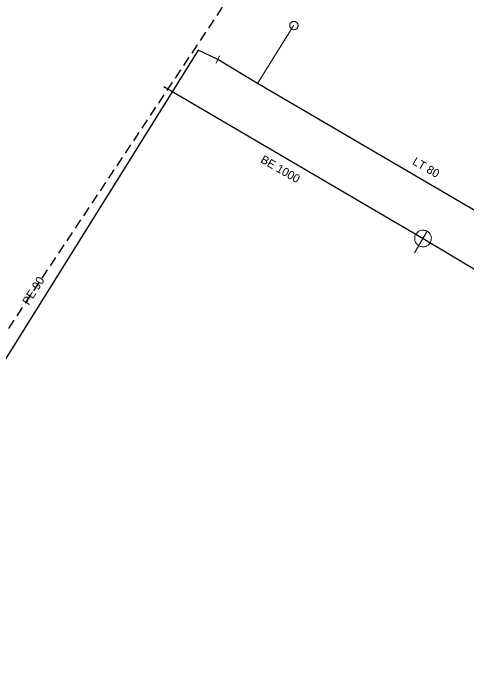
# Model space of a CAD drawing. Extents: x -791337 to -790755, y -988454 to -987923.
# Drawn here: x -791283 to -791228.7, y -988043.6 to -987964.2 of the extents above; entities that cross this region are included whole.
import ezdxf

# ---------------------------------------------------------------- set-up
doc = ezdxf.new("R2010")
doc.units = 0
doc.header["$LTSCALE"] = 0.4
doc.linetypes.add('MEDIUM_DASHED', pattern=[4.5, 3, -1.5])
for name, color, linetype, lineweight in [('1', 7, 'Continuous', 13), ('13', 7, 'Continuous', 13), ('14', 7, 'Continuous', 25), ('17', 7, 'Continuous', 25), ('22', 7, 'Continuous', 13), ('23', 7, 'Continuous', 13), ('34', 7, 'Continuous', 13), ('63', 7, 'MEDIUM_DASHED', 25)]:
    doc.layers.add(name, color=color, linetype=linetype, lineweight=lineweight)

msp = doc.modelspace()

# ---------------------------------------------------------------- linework, layer by layer
at = {"layer": '13'}
msp.add_line((-791249.419, -987965.689), (-791253.76, -987972.659), dxfattribs=at)
at = {"layer": '14'}
for p, q in [((-791265, -987973), (-791233.94, -987991.21)), ((-791233.94, -987991.21), (-791199.109, -988012.02))]:
    msp.add_line(p, q, dxfattribs=at)
at = {"layer": '17'}
for points in [[(-791258.52, -987969.789), (-791260.859, -987968.66), (-791297.14, -988026.69), (-791304.129, -988037.219)], [(-791197.89, -988005.699), (-791208.364, -987999.238), (-791208.76, -987998.997), (-791217.801, -987993.705), (-791253.76, -987972.659), (-791258.52, -987969.789)]]:
    msp.add_lwpolyline(points, dxfattribs=at)
at = {"layer": '22'}
msp.add_line((-791234.951, -987992.935), (-791233.434, -987990.347), dxfattribs=at)
msp.add_lwpolyline([(-791233.077, -987991.716), (-791233.027, -987991.619), (-791232.988, -987991.516), (-791232.96, -987991.41), (-791232.944, -987991.302), (-791232.94, -987991.192), (-791232.948, -987991.083), (-791232.968, -987990.975), (-791232.999, -987990.871), (-791233.042, -987990.77), (-791233.095, -987990.675), (-791233.159, -987990.585), (-791233.233, -987990.504), (-791233.314, -987990.431), (-791233.403, -987990.367), (-791233.499, -987990.313), (-791233.599, -987990.27), (-791233.704, -987990.238), (-791233.811, -987990.218), (-791233.921, -987990.21), (-791234.029, -987990.214), (-791234.138, -987990.23), (-791234.244, -987990.257), (-791234.347, -987990.297), (-791234.444, -987990.346), (-791234.535, -987990.407), (-791234.619, -987990.477), (-791234.696, -987990.556), (-791234.762, -987990.642), (-791234.82, -987990.736), (-791234.866, -987990.835), (-791234.902, -987990.938), (-791234.926, -987991.045), (-791234.938, -987991.153), (-791234.939, -987991.263), (-791234.926, -987991.372), (-791234.903, -987991.479), (-791234.868, -987991.583), (-791234.821, -987991.682), (-791234.765, -987991.775), (-791234.698, -987991.862), (-791234.622, -987991.941), (-791234.538, -987992.011), (-791234.446, -987992.072), (-791234.349, -987992.122), (-791234.247, -987992.161), (-791234.142, -987992.189), (-791234.033, -987992.205), (-791233.923, -987992.21), (-791233.814, -987992.202), (-791233.706, -987992.182), (-791233.601, -987992.151), (-791233.501, -987992.108), (-791233.405, -987992.055), (-791233.316, -987991.991), (-791233.234, -987991.919), (-791233.161, -987991.837), (-791233.097, -987991.748)], close=True, dxfattribs=at)
at = {"layer": '23'}
for points in [[(-791249.157, -987965.289), (-791249.203, -987965.265), (-791249.253, -987965.245), (-791249.302, -987965.233), (-791249.354, -987965.224), (-791249.406, -987965.22), (-791249.459, -987965.223), (-791249.51, -987965.231), (-791249.56, -987965.244), (-791249.61, -987965.262), (-791249.656, -987965.285), (-791249.701, -987965.313), (-791249.743, -987965.346), (-791249.78, -987965.382), (-791249.812, -987965.422), (-791249.842, -987965.465), (-791249.866, -987965.513), (-791249.885, -987965.56), (-791249.899, -987965.613), (-791249.908, -987965.662), (-791249.912, -987965.715), (-791249.908, -987965.769), (-791249.901, -987965.82), (-791249.887, -987965.871), (-791249.87, -987965.92), (-791249.847, -987965.966), (-791249.817, -987966.011), (-791249.786, -987966.051), (-791249.749, -987966.088), (-791249.708, -987966.121), (-791249.665, -987966.151), (-791249.619, -987966.175), (-791249.57, -987966.194), (-791249.519, -987966.209), (-791249.468, -987966.217), (-791249.417, -987966.219), (-791249.364, -987966.217), (-791249.312, -987966.21), (-791249.26, -987966.197), (-791249.212, -987966.178)], [(-791249.212, -987966.178), (-791249.166, -987966.156), (-791249.121, -987966.127), (-791249.08, -987966.096), (-791249.043, -987966.057), (-791249.01, -987966.017), (-791248.981, -987965.974), (-791248.957, -987965.928), (-791248.937, -987965.879), (-791248.923, -987965.828), (-791248.915, -987965.777), (-791248.911, -987965.724), (-791248.913, -987965.673), (-791248.922, -987965.621), (-791248.934, -987965.57), (-791248.952, -987965.522), (-791248.976, -987965.474), (-791249.004, -987965.43), (-791249.037, -987965.389), (-791249.074, -987965.352), (-791249.114, -987965.319), (-791249.157, -987965.289), (-791249.203, -987965.265), (-791249.253, -987965.245), (-791249.302, -987965.233), (-791249.354, -987965.224), (-791249.406, -987965.22), (-791249.459, -987965.223), (-791249.51, -987965.231), (-791249.56, -987965.244), (-791249.61, -987965.262), (-791249.656, -987965.285), (-791249.701, -987965.313), (-791249.743, -987965.346), (-791249.78, -987965.382), (-791249.812, -987965.422), (-791249.842, -987965.465), (-791249.866, -987965.513), (-791249.885, -987965.56), (-791249.899, -987965.613)], [(-791249.899, -987965.613), (-791249.908, -987965.662), (-791249.912, -987965.715), (-791249.908, -987965.769), (-791249.901, -987965.82), (-791249.887, -987965.871), (-791249.87, -987965.92), (-791249.847, -987965.966), (-791249.817, -987966.011), (-791249.786, -987966.051), (-791249.749, -987966.088), (-791249.708, -987966.121), (-791249.665, -987966.151), (-791249.619, -987966.175), (-791249.57, -987966.194), (-791249.519, -987966.209), (-791249.468, -987966.217), (-791249.417, -987966.219), (-791249.364, -987966.217), (-791249.312, -987966.21), (-791249.26, -987966.197), (-791249.212, -987966.178), (-791249.166, -987966.156), (-791249.121, -987966.127), (-791249.08, -987966.096), (-791249.043, -987966.057), (-791249.01, -987966.017), (-791248.981, -987965.974), (-791248.957, -987965.928), (-791248.937, -987965.879), (-791248.923, -987965.828), (-791248.915, -987965.777), (-791248.911, -987965.724), (-791248.913, -987965.673), (-791248.922, -987965.621), (-791248.934, -987965.57), (-791248.952, -987965.522), (-791248.976, -987965.474), (-791249.004, -987965.43), (-791249.037, -987965.389)], [(-791249.037, -987965.389), (-791249.074, -987965.352), (-791249.114, -987965.319), (-791249.157, -987965.289)]]:
    msp.add_lwpolyline(points, dxfattribs=at)
at = {"layer": '34'}
msp.add_line((-791258.736, -987970.239), (-791258.302, -987969.338), dxfattribs=at)
at = {"layer": '63'}
msp.add_lwpolyline([(-791231.02, -987923.132), (-790755.118, -988202.253), (-790755.118, -988202.253), (-790903.053, -988400.429), (-790903.053, -988400.429), (-791331.504, -988073.857), (-791331.504, -988073.857)], close=True, dxfattribs=at)

# ---------------------------------------------------------------- texts
at = {"layer": '1'}
for s, rotation, p in [('BE 1000 ', 330, (-791253.493, -987982.047)), ('LT 80 ', 330, (-791235.297, -987982.277)), ('PE 90 ', 58, (-791281.16, -987999.271))]:
    msp.add_text(s, height=1, rotation=rotation, dxfattribs=at).set_placement(p)

doc.saveas('drawing.dxf')
